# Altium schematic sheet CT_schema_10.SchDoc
size 278 x 170 mm
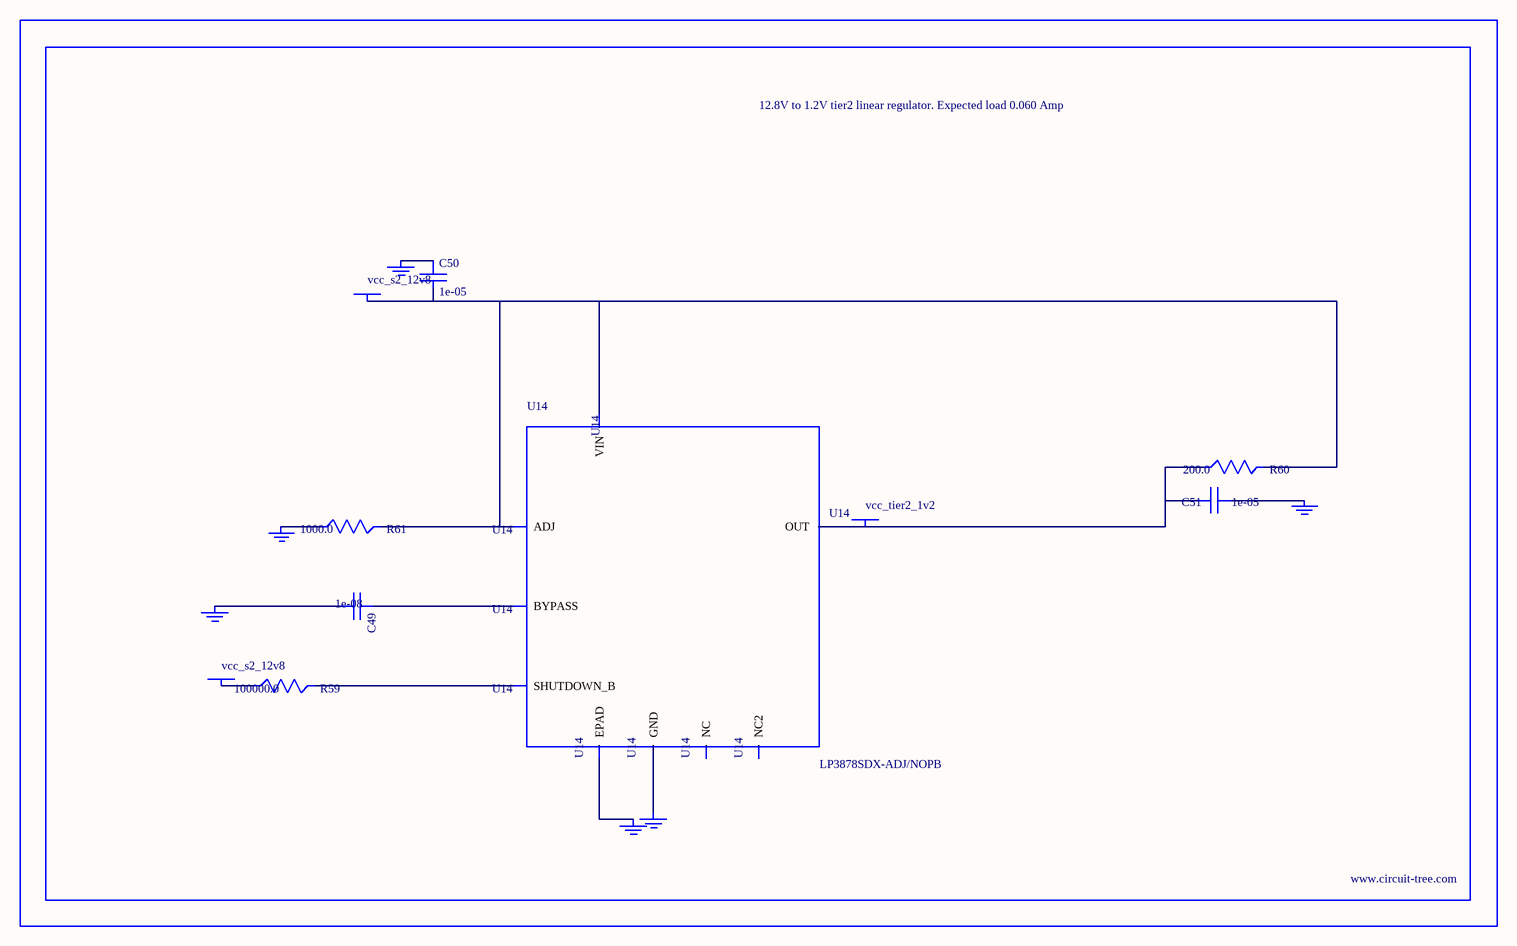
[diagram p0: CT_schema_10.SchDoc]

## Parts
BORDER9  (no value)
C49  1e-08  [C0402]
C50  1e-05  [C1210]
C51  1e-05  [C0805]
GND_INSTANCE_9_0  (no value)
GND_INSTANCE_9_1  (no value)
GND_INSTANCE_9_2  (no value)
GND_INSTANCE_9_3  (no value)
GND_INSTANCE_9_4  (no value)
GND_INSTANCE_9_5  (no value)
POWER_INSTANCE_9_0  vcc_s2_12v8
POWER_INSTANCE_9_1  vcc_s2_12v8
POWER_INSTANCE_9_2  vcc_tier2_1v2
R59  100000.0  [R0603]
R60  200.0  [R0603]
R61  1000.0  [R0603]
U14  LP3878SDX-ADJ/NOPB  [WSON-8]

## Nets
NetC49_1: C49.1 U14.1(BYPASS)
NetC49_2: C49.2 GND_INSTANCE_9_0.0(GND)
NetC50_1: C50.1 GND_INSTANCE_9_1.0(GND)
NetC50_2: C50.2 POWER_INSTANCE_9_0.0(PWR) R60.2 R61.2 U14.4(VIN) U14.6(ADJ)
NetC51_1: C51.1 GND_INSTANCE_9_2.0(GND)
NetC51_2: C51.2 POWER_INSTANCE_9_2.0(PWR) R60.1 U14.5(OUT)
NetGND_INSTANCE_9_3_0: GND_INSTANCE_9_3.0(GND) R61.1
NetGND_INSTANCE_9_4_0: GND_INSTANCE_9_4.0(GND) U14.PAD(EPAD)
NetGND_INSTANCE_9_5_0: GND_INSTANCE_9_5.0(GND) U14.3(GND)
NetPOWER_INSTANCE_9_1_0: POWER_INSTANCE_9_1.0(PWR) R59.1
NetR59_2: R59.2 U14.8(SHUTDOWN_B)

Not connected (* = marked no-connect by the designer): U14 2(NC) 7(NC2)

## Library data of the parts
BORDER9 = BORDER_PAGE9
C49 = C0402C103K3RAC
C50 = C1210C106K5PACTU
C51 = GRM219R60J106ME19D
GND_INSTANCE_9_0-GND_INSTANCE_9_5 = GND
POWER_INSTANCE_9_0-POWER_INSTANCE_9_2 = PWR
R59 = RC0603JR-07100KL
R60 = RC0603JR-07200RL
R61 = RC0603JR-071KL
